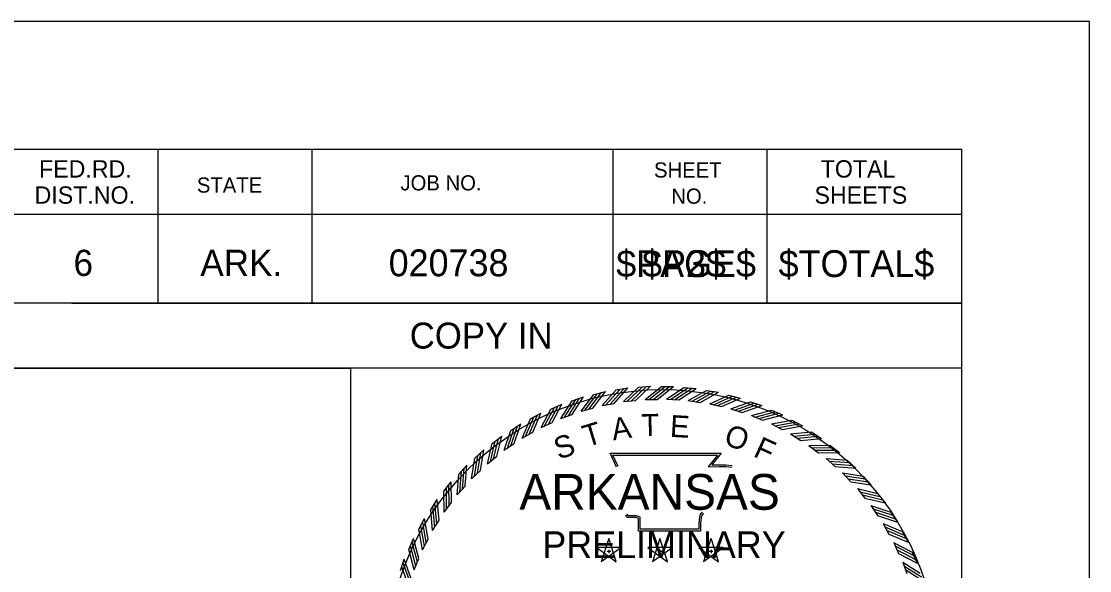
# Model space of a CAD drawing. Extents: x 0 to 1228743, y 0 to 152440.
# Drawn here: x 29.181 to 34, y 19.522 to 22 of the extents above; entities that cross this region are included whole.
import ezdxf

# ---------------------------------------------------------------- set-up
doc = ezdxf.new("R2010")
doc.units = 0
for name, color, linetype in [('R_Border', 7, 'Continuous'), ('R_Copy In', 7, 'Continuous'), ('R_Draft', 7, 'Continuous'), ('R_No Plot', 7, 'Continuous'), ('R_P1_To_Summary', 7, 'Continuous'), ('R_P2_Summary_To_End_PP', 7, 'Continuous'), ('R_P3_Cross_Sections', 7, 'Continuous'), ('STAMP_JUSTIN', 7, 'Continuous')]:
    doc.layers.add(name, color=color, linetype=linetype)

msp = doc.modelspace()

# ---------------------------------------------------------------- linework, layer by layer
at = {"layer": 'R_Border'}
for p, q in [((1.516, 21.4232), (33.4232, 21.4232)), ((29.7972, 21.4232), (29.7972, 20.7292)), ((30.4912, 21.4232), (30.4912, 20.7292)), ((31.8492, 21.4232), (31.8492, 20.7292)), ((32.5432, 21.4232), (32.5432, 20.7292)), ((33.4232, 0.5768), (33.4232, 21.4232)), ((33.4232, 21.1292), (29.1132, 21.1292)), ((33.4232, 21.1312), (33.4232, 21.1312)), ((33.4232, 20.7292), (29.1132, 20.7292)), ((29.4092, 20.7292), (33.4232, 20.7292)), ((33.4232, 20.4352), (27.1592, 20.4352))]:
    msp.add_line(p, q, dxfattribs=at)
msp.add_lwpolyline([(34, 22), (0, 22), (0, 0), (34, 0)], close=True, dxfattribs=at)
at = {"layer": 'R_Draft'}
msp.add_circle((32.0709, 19.0937), 1.2447, dxfattribs=at)
at = {"layer": 'R_No Plot'}
for points in [[(33.4232, 17.4053), (33.4232, 10.8708), (1.516, 10.8708), (1.516, 21.4232), (27.1592, 21.4232), (27.1592, 20.4352), (28.7492, 20.4352), (30.6666, 20.4352)], [(30.6666, 20.4352), (30.6666, 17.4053), (33.4232, 17.4053)]]:
    msp.add_lwpolyline(points, dxfattribs=at)
at = {"layer": 'STAMP_JUSTIN'}
for p, q in [((31.864, 20.3368), (31.9175, 20.3463)), ((31.9657, 20.349), (32.0198, 20.354)), ((32.0686, 20.352), (32.123, 20.352)), ((32.1704, 20.3479), (32.2246, 20.3439)), ((32.272, 20.3347), (32.3257, 20.3263)), ((31.6653, 20.2876), (31.7166, 20.3057)), ((31.7637, 20.3163), (31.8162, 20.3301)), ((31.8972, 20.2846), (31.9514, 20.2896)), ((31.9945, 20.2942), (32.0489, 20.2942)), ((32.0922, 20.2957), (32.1465, 20.2917)), ((32.1897, 20.2891), (32.2435, 20.2807)), ((32.3721, 20.3132), (32.4249, 20.3003)), ((31.5697, 20.2508), (31.6193, 20.2731)), ((31.7067, 20.2415), (31.7593, 20.2554)), ((31.801, 20.267), (31.8547, 20.2765)), ((32.2864, 20.2746), (32.3393, 20.2617)), ((32.3815, 20.252), (32.4332, 20.2348)), ((32.4701, 20.2835), (32.5217, 20.2663)), ((32.5654, 20.2458), (32.6153, 20.2244)), ((31.4775, 20.2063), (31.525, 20.2326)), ((31.5258, 20.1677), (31.5755, 20.19)), ((31.6147, 20.2083), (31.6661, 20.2265)), ((32.4745, 20.2217), (32.5245, 20.2003)), ((32.6572, 20.2003), (32.7052, 20.1749)), ((31.3892, 20.1543), (31.4344, 20.1845)), ((31.4406, 20.1198), (31.4882, 20.1462)), ((32.5646, 20.1839), (32.6127, 20.1584)), ((32.7449, 20.1474), (32.7906, 20.1181)), ((31.3056, 20.0952), (31.3481, 20.129)), ((31.3596, 20.0651), (31.4049, 20.0953)), ((32.6513, 20.1387), (32.6971, 20.1093)), ((31.2271, 20.0294), (31.2667, 20.0666)), ((32.7339, 20.0865), (32.7772, 20.0535)), ((32.8279, 20.0875), (32.8711, 20.0545)), ((31.1543, 19.9574), (31.1907, 19.9977)), ((31.2834, 20.0039), (31.3261, 20.0377)), ((32.812, 20.0277), (32.8524, 19.9912)), ((32.9058, 20.0209), (32.9461, 19.9844)), ((31.2125, 19.9365), (31.2522, 19.9738)), ((32.8849, 19.9626), (32.9222, 19.9229)), ((31.0877, 19.8796), (31.1206, 19.9227)), ((31.1474, 19.8636), (31.184, 19.904)), ((32.9778, 19.9481), (33.015, 19.9084)), ((32.9522, 19.8917), (32.9861, 19.8491)), ((33.0436, 19.8696), (33.0774, 19.827)), ((31.0277, 19.7965), (31.057, 19.8423)), ((31.0886, 19.7855), (31.1217, 19.8288)), ((33.0135, 19.8155), (33.0437, 19.7702)), ((30.9748, 19.7088), (31.0003, 19.7568)), ((33.1027, 19.7859), (33.1329, 19.7407)), ((31.0364, 19.7029), (31.0658, 19.7487)), ((33.0682, 19.7346), (33.0946, 19.6869)), ((30.9294, 19.617), (30.9507, 19.6669)), ((30.9912, 19.6162), (31.0167, 19.6643)), ((31.8312, 19.6664), (31.7972, 19.5621)), ((31.865, 19.5622), (31.8312, 19.6665)), ((32.0617, 19.6664), (32.0277, 19.5621)), ((32.0955, 19.5622), (32.0617, 19.6665)), ((32.2921, 19.6664), (32.2581, 19.5621)), ((32.326, 19.5622), (32.2922, 19.6665)), ((33.1547, 19.6977), (33.181, 19.6501)), ((31.886, 19.6266), (31.7763, 19.6267)), ((31.7764, 19.6266), (31.865, 19.562)), ((31.7973, 19.5622), (31.8861, 19.6265)), ((31.8313, 19.6149), (31.8313, 19.6011)), ((32.1165, 19.6266), (32.0068, 19.6267)), ((32.0069, 19.6266), (32.0955, 19.562)), ((32.0278, 19.5622), (32.1166, 19.6265)), ((32.0618, 19.6149), (32.0618, 19.6011)), ((32.3469, 19.6266), (32.2372, 19.6267)), ((32.2373, 19.6266), (32.326, 19.562)), ((32.2583, 19.5622), (32.3471, 19.6265)), ((32.2922, 19.6149), (32.2922, 19.6011)), ((33.1161, 19.6493), (33.1384, 19.5996)), ((30.8917, 19.5218), (30.9088, 19.5733)), ((30.9534, 19.5261), (30.9748, 19.5761)), ((31.8234, 19.6091), (31.8397, 19.6091)), ((32.0538, 19.6091), (32.0701, 19.6091)), ((32.2843, 19.6091), (32.3006, 19.6091)), ((33.1992, 19.6054), (33.2215, 19.5558)), ((33.1567, 19.5604), (33.1749, 19.5091))]:
    msp.add_line(p, q, dxfattribs=at)
for points in [[(31.801, 20.2669), (31.8639, 20.3368)], [(31.8182, 20.2698), (31.8812, 20.3396)], [(31.8367, 20.2735), (31.8997, 20.3433)], [(31.8546, 20.2765), (31.9176, 20.3463)], [(31.8971, 20.2845), (31.9656, 20.3489)], [(31.9146, 20.286), (31.9831, 20.3504)], [(31.9333, 20.2881), (32.0018, 20.3525)], [(31.9514, 20.2896), (32.0199, 20.354)], [(31.9944, 20.2941), (32.0685, 20.3519)], [(32.0119, 20.294), (32.086, 20.3518)], [(32.0308, 20.2944), (32.1049, 20.3522)], [(32.0489, 20.2942), (32.123, 20.352)], [(32.0921, 20.2957), (32.1703, 20.3479)], [(32.1096, 20.2942), (32.1877, 20.3464)], [(32.1284, 20.2932), (32.2066, 20.3455)], [(32.1465, 20.2917), (32.2246, 20.344)], [(32.1897, 20.2891), (32.2719, 20.3347)], [(31.6147, 20.2083), (31.6653, 20.2875)], [(31.6312, 20.214), (31.6818, 20.2932)], [(31.6489, 20.2206), (31.6995, 20.2999)], [(31.666, 20.2265), (31.7166, 20.3057)], [(31.7066, 20.2415), (31.7636, 20.3162)], [(31.7236, 20.2457), (31.7805, 20.3205)], [(31.7417, 20.251), (31.7987, 20.3257)], [(31.7593, 20.2554), (31.8162, 20.3302)], [(32.2069, 20.2862), (32.2891, 20.3318)], [(32.2256, 20.2837), (32.3079, 20.3293)], [(32.2435, 20.2807), (32.3257, 20.3263)], [(32.2863, 20.2745), (32.372, 20.3132)], [(32.3033, 20.2702), (32.389, 20.3089)], [(32.3217, 20.2662), (32.4074, 20.3048)], [(32.3393, 20.2617), (32.425, 20.3004)], [(31.5258, 20.1676), (31.5697, 20.2508)], [(31.5418, 20.1746), (31.5857, 20.2578)], [(31.5588, 20.1828), (31.6027, 20.2659)], [(31.5754, 20.19), (31.6193, 20.2732)], [(32.3814, 20.252), (32.47, 20.2834)], [(32.398, 20.2463), (32.4866, 20.2778)], [(32.416, 20.2408), (32.5046, 20.2722)], [(32.4331, 20.2349), (32.5218, 20.2663)], [(32.4744, 20.2217), (32.5653, 20.2457)], [(32.4904, 20.2147), (32.5813, 20.2387)], [(31.4405, 20.1198), (31.4774, 20.2062)], [(31.4559, 20.1281), (31.4928, 20.2146)], [(31.4722, 20.1376), (31.5091, 20.2241)], [(31.4882, 20.1462), (31.525, 20.2327)], [(32.5079, 20.2077), (32.5988, 20.2317)], [(32.5245, 20.2004), (32.6154, 20.2244)], [(32.5645, 20.1839), (32.6571, 20.2003)], [(32.5799, 20.1755), (32.6725, 20.192)], [(31.3596, 20.065), (31.3892, 20.1542)], [(31.3742, 20.0746), (31.4038, 20.1638)], [(31.3897, 20.0854), (31.4193, 20.1746)], [(31.4048, 20.0953), (31.4345, 20.1845)], [(32.5968, 20.1671), (32.6893, 20.1835)], [(32.6127, 20.1585), (32.7052, 20.1749)], [(32.6512, 20.1387), (32.7448, 20.1474)], [(31.2834, 20.0038), (31.3055, 20.0952)], [(31.2972, 20.0145), (31.3193, 20.1059)], [(31.3117, 20.0266), (31.3339, 20.118)], [(31.326, 20.0377), (31.3481, 20.1291)], [(32.6658, 20.1291), (32.7594, 20.1378)], [(32.6819, 20.1193), (32.7756, 20.128)], [(32.6971, 20.1094), (32.7907, 20.1181)], [(31.2389, 19.9615), (31.2534, 20.0544)], [(31.2522, 19.9738), (31.2667, 20.0667)], [(31.8662, 19.9883), (31.8372, 20.051), (32.3384, 20.0513), (32.2965, 19.9987), (32.3305, 19.9992), (32.359, 19.9995), (32.3874, 19.9964)], [(32.7338, 20.0865), (32.8279, 20.0875)], [(32.7476, 20.0758), (32.8417, 20.0767)], [(32.7629, 20.0647), (32.8569, 20.0656)], [(32.7772, 20.0535), (32.8712, 20.0545)], [(31.1839, 19.904), (31.1907, 19.9978)], [(31.2125, 19.9365), (31.227, 20.0293)], [(31.2254, 19.9483), (31.2399, 20.0412)], [(31.8734, 19.9916), (31.8496, 20.0431), (32.3219, 20.0434), (32.2798, 19.9906), (32.3306, 19.9912), (32.3586, 19.9916), (32.3865, 19.9885)], [(32.8119, 20.0277), (32.9057, 20.0209)], [(32.8248, 20.0159), (32.9185, 20.009)], [(32.8391, 20.0035), (32.9328, 19.9967)], [(31.1474, 19.8635), (31.1542, 19.9573)], [(31.1593, 19.8764), (31.1661, 19.9702)], [(31.1716, 19.8907), (31.1784, 19.9844)], [(32.8524, 19.9912), (32.9461, 19.9844)], [(32.8848, 19.9626), (32.9777, 19.9481)], [(32.8967, 19.9498), (32.9896, 19.9352)], [(31.1105, 19.8145), (31.1095, 19.9085)], [(31.1216, 19.8288), (31.1206, 19.9228)], [(32.9099, 19.9363), (33.0028, 19.9217)], [(32.9222, 19.923), (33.0151, 19.9084)], [(31.0886, 19.7854), (31.0876, 19.8795)], [(31.0993, 19.7992), (31.0984, 19.8933)], [(32.9522, 19.8918), (33.0435, 19.8696)], [(32.9629, 19.878), (33.0543, 19.8558)], [(32.975, 19.8634), (33.0663, 19.8413)], [(31.046, 19.7174), (31.0373, 19.811)], [(31.0558, 19.7336), (31.0471, 19.8272)], [(31.0657, 19.7487), (31.057, 19.8423)], [(32.9861, 19.8491), (33.0775, 19.827)], [(33.0134, 19.8156), (33.1026, 19.7859)], [(31.0167, 19.6643), (31.0002, 19.7569)], [(31.0364, 19.7028), (31.0277, 19.7964)], [(32.2594, 19.7783), (32.2508, 19.7713), (32.248, 19.761), (32.2452, 19.735), (32.2452, 19.7003), (31.9654, 19.7003), (31.9654, 19.7471), (31.9654, 19.7575), (31.9541, 19.761), (31.9143, 19.761), (31.9072, 19.7717)], [(32.2544, 19.7845), (32.2438, 19.7759), (32.2402, 19.7624), (32.2372, 19.7354), (32.2372, 19.7083), (31.9733, 19.7083), (31.9733, 19.7471), (31.9733, 19.7634), (31.9552, 19.7689), (31.9185, 19.7689), (31.9138, 19.7761)], [(33.023, 19.8009), (33.1122, 19.7713)], [(33.0338, 19.7855), (33.123, 19.7558)], [(33.0437, 19.7703), (33.1329, 19.7407)], [(30.9913, 19.6161), (30.9748, 19.7087)], [(30.9996, 19.6315), (30.9832, 19.7241)], [(31.008, 19.6484), (30.9916, 19.7409)], [(33.0681, 19.7346), (33.1546, 19.6977)], [(33.0765, 19.7192), (33.1629, 19.6823)], [(30.9747, 19.5761), (30.9507, 19.667)], [(33.086, 19.7029), (33.1724, 19.666)], [(33.0946, 19.687), (33.1811, 19.6501)], [(30.9534, 19.526), (30.9294, 19.6169)], [(30.9604, 19.542), (30.9364, 19.6329)], [(30.9675, 19.5595), (30.9435, 19.6504)], [(33.116, 19.6494), (33.1991, 19.6055)], [(33.123, 19.6333), (33.2062, 19.5894)], [(33.1311, 19.6163), (33.2143, 19.5724)], [(30.9402, 19.4848), (30.9088, 19.5734)], [(33.1384, 19.5997), (33.2216, 19.5558)], [(30.9288, 19.4496), (30.8974, 19.5382)], [(30.9344, 19.4676), (30.9029, 19.5562)], [(33.1567, 19.5605), (33.2359, 19.5098)], [(33.1623, 19.5439), (33.2416, 19.4933)], [(33.169, 19.5263), (33.2483, 19.4756)]]:
    msp.add_lwpolyline(points, dxfattribs=at)

# ---------------------------------------------------------------- texts
at = {"layer": 'R_Border'}
for s, height, p in [('FED.RD.', 0.07819, (29.261, 21.2952)), ('SHEET', 0.0684, (32.035, 21.2952)), ('TOTAL', 0.07819, (32.787, 21.2952)), ('JOB NO.', 0.0684, (30.8913, 21.2372)), ('DIST.NO.', 0.07819, (29.241, 21.1772)), ('STATE', 0.0684, (29.973, 21.2272)), ('SHEETS', 0.07819, (32.759, 21.1772)), ('NO.', 0.0684, (32.113, 21.1772)), ('6', 0.1183, (29.4168, 20.8513)), ('ARK.', 0.11831, (29.9887, 20.8513)), ('020738', 0.1211, (30.8382, 20.8498)), ('$TOTAL$', 0.1211, (32.597, 20.8463))]:
    msp.add_text(s, height=height, dxfattribs=at).set_placement(p)
at = {"layer": 'R_Copy In'}
msp.add_text('COPY IN', height=0.11724, rotation=360, dxfattribs=at).set_placement((30.9331, 20.5236))
at = {"layer": 'R_Draft'}
msp.add_text('PRELIMINARY', height=0.121097, dxfattribs=at).set_placement((31.5312, 19.5781))
at = {"layer": 'R_P1_To_Summary'}
msp.add_text('$PAGE$', height=0.1211, dxfattribs=at).set_placement((31.8646, 20.8463))
at = {"layer": 'R_P2_Summary_To_End_PP'}
msp.add_text('$P2$', height=0.1211, dxfattribs=at).set_placement((31.981, 20.8463))
at = {"layer": 'R_P3_Cross_Sections'}
msp.add_text('$P3$', height=0.1211, dxfattribs=at).set_placement((31.981, 20.8463))
at = {"layer": 'STAMP_JUSTIN'}
for s, rotation, p in [('T', 16.9015, (31.7309, 20.0776)), ('A', 8.6788, (31.8509, 20.109)), ('T', 1.4789, (31.9785, 20.1286)), ('E', 356.672, (32.1051, 20.1256)), ('O', 341.2218, (32.3451, 20.0917)), ('S', 19.7726, (31.6052, 20.0212)), ('F', 335.3628, (32.4783, 20.0396))]:
    msp.add_text(s, height=0.0989, rotation=rotation, dxfattribs=at).set_placement(p)
msp.add_text('ARKANSAS', height=0.16134, dxfattribs=at).set_placement((31.4275, 19.7963))

doc.saveas('drawing.dxf')
